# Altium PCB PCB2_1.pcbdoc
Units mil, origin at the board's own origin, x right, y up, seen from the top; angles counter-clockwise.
Board outline 2187.3 x 2736.54 mil, 4 copper layers (Top Layer, 3.3V, GND, Bottom Layer); 82 components, 93 nets, 404 pads, 111 vias.
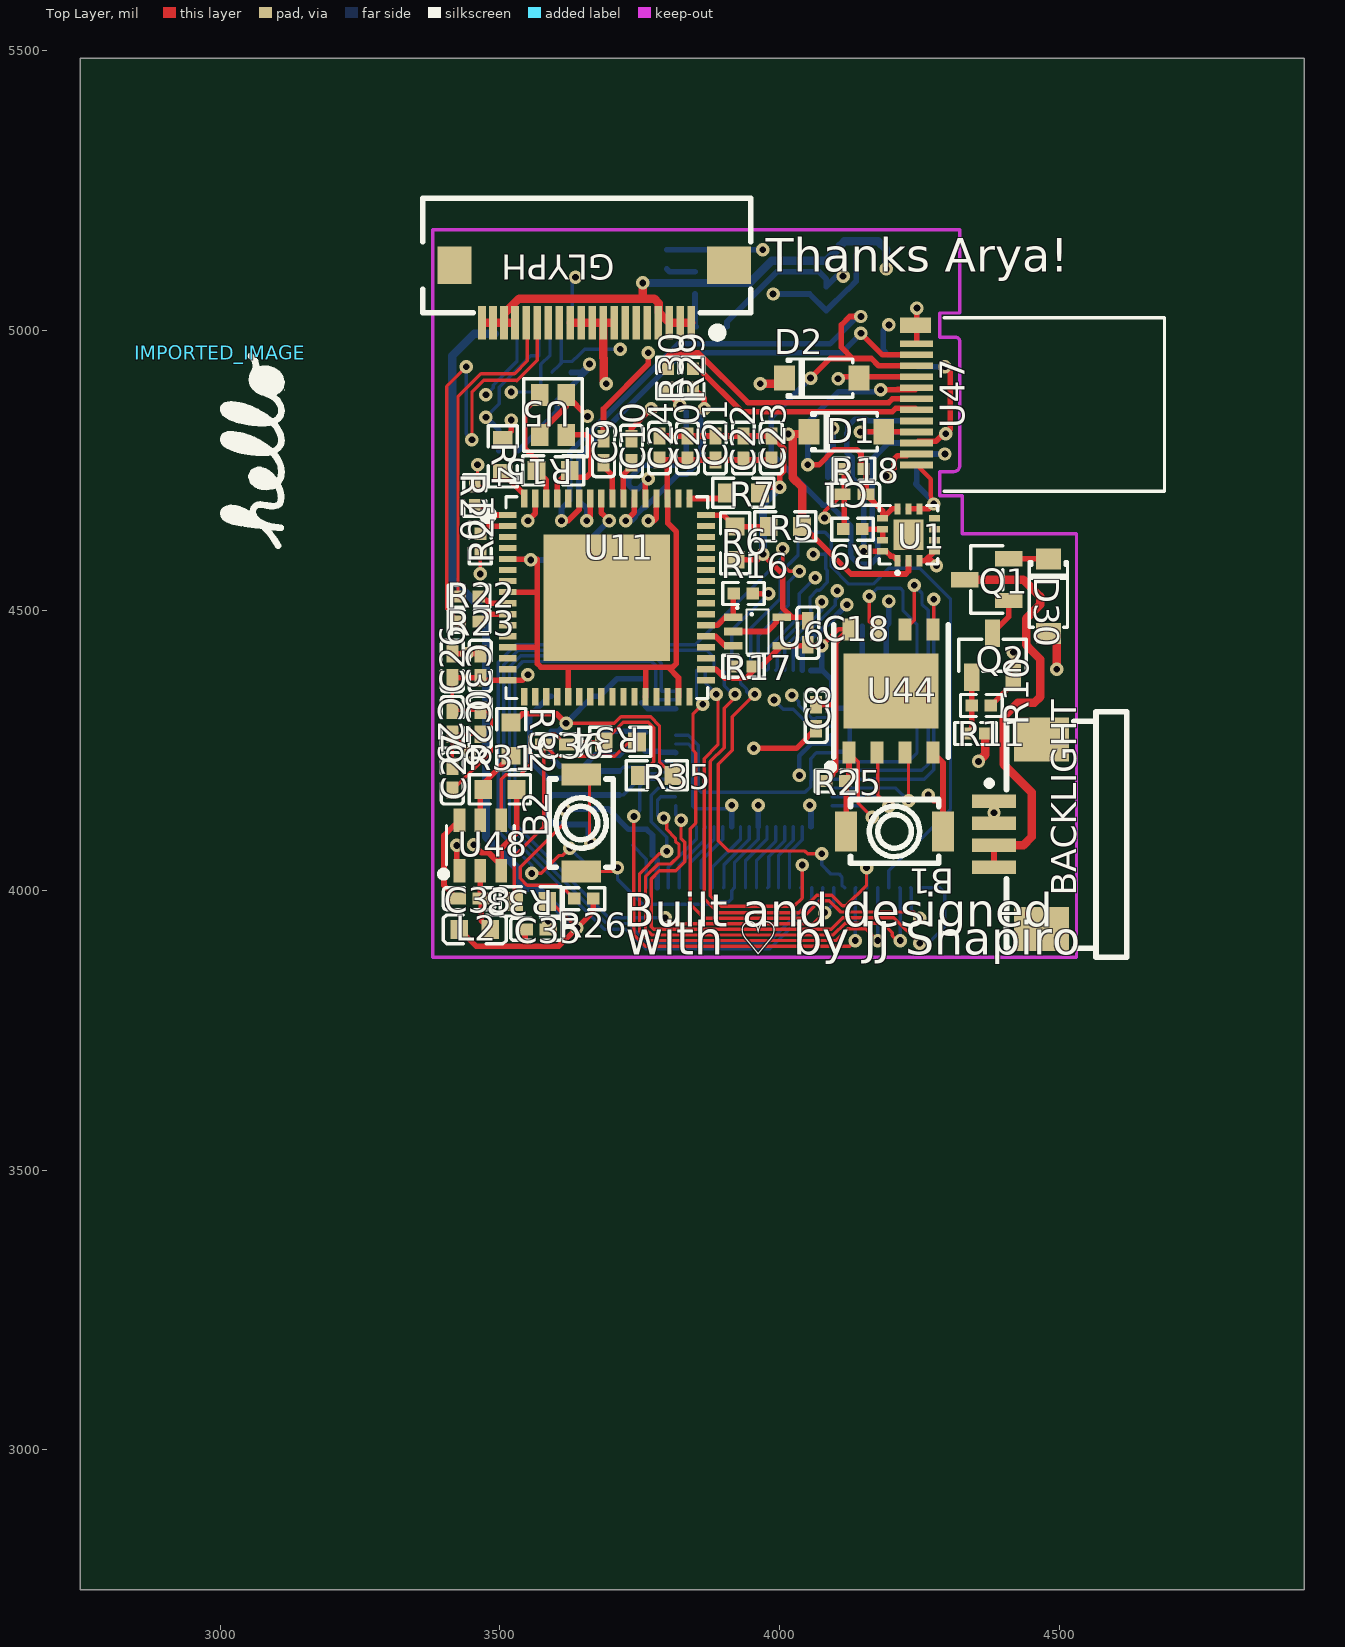
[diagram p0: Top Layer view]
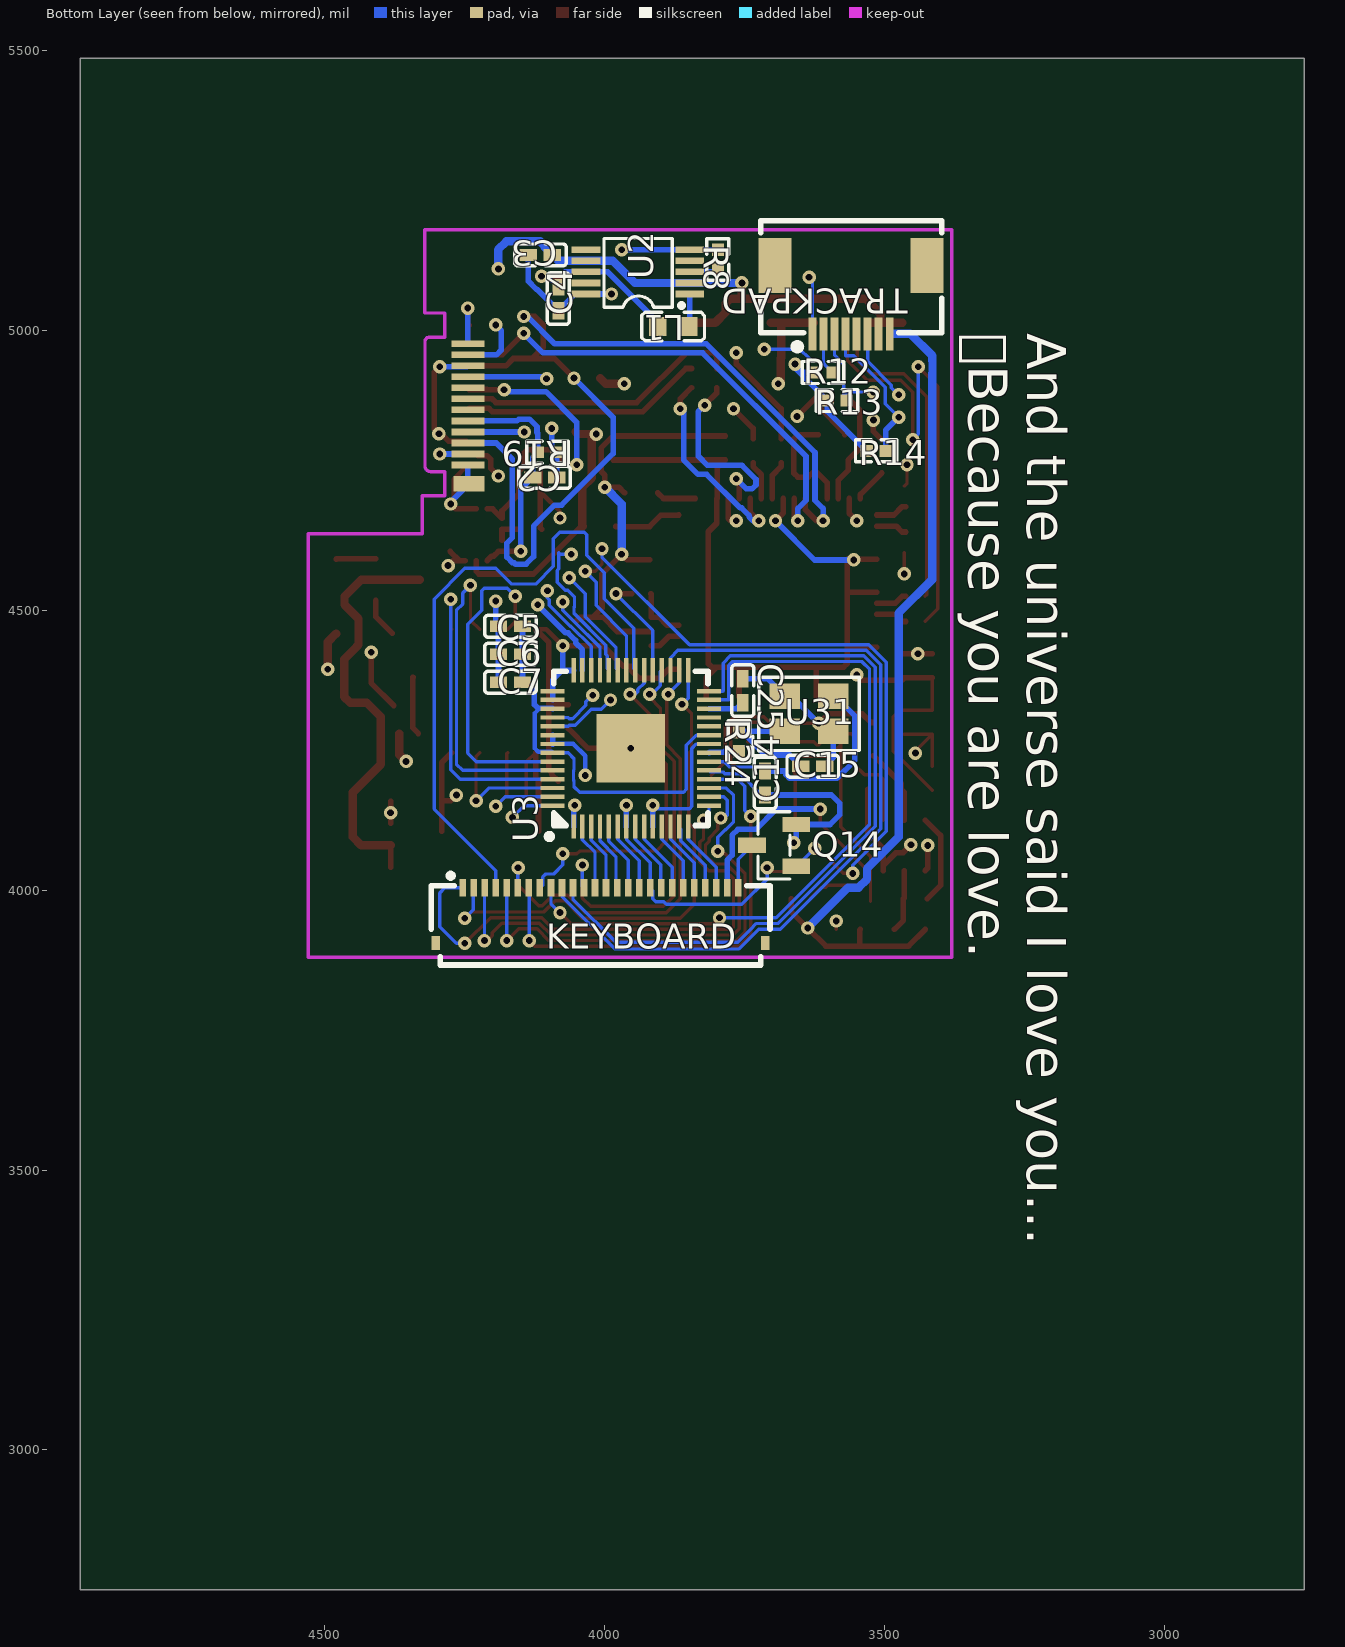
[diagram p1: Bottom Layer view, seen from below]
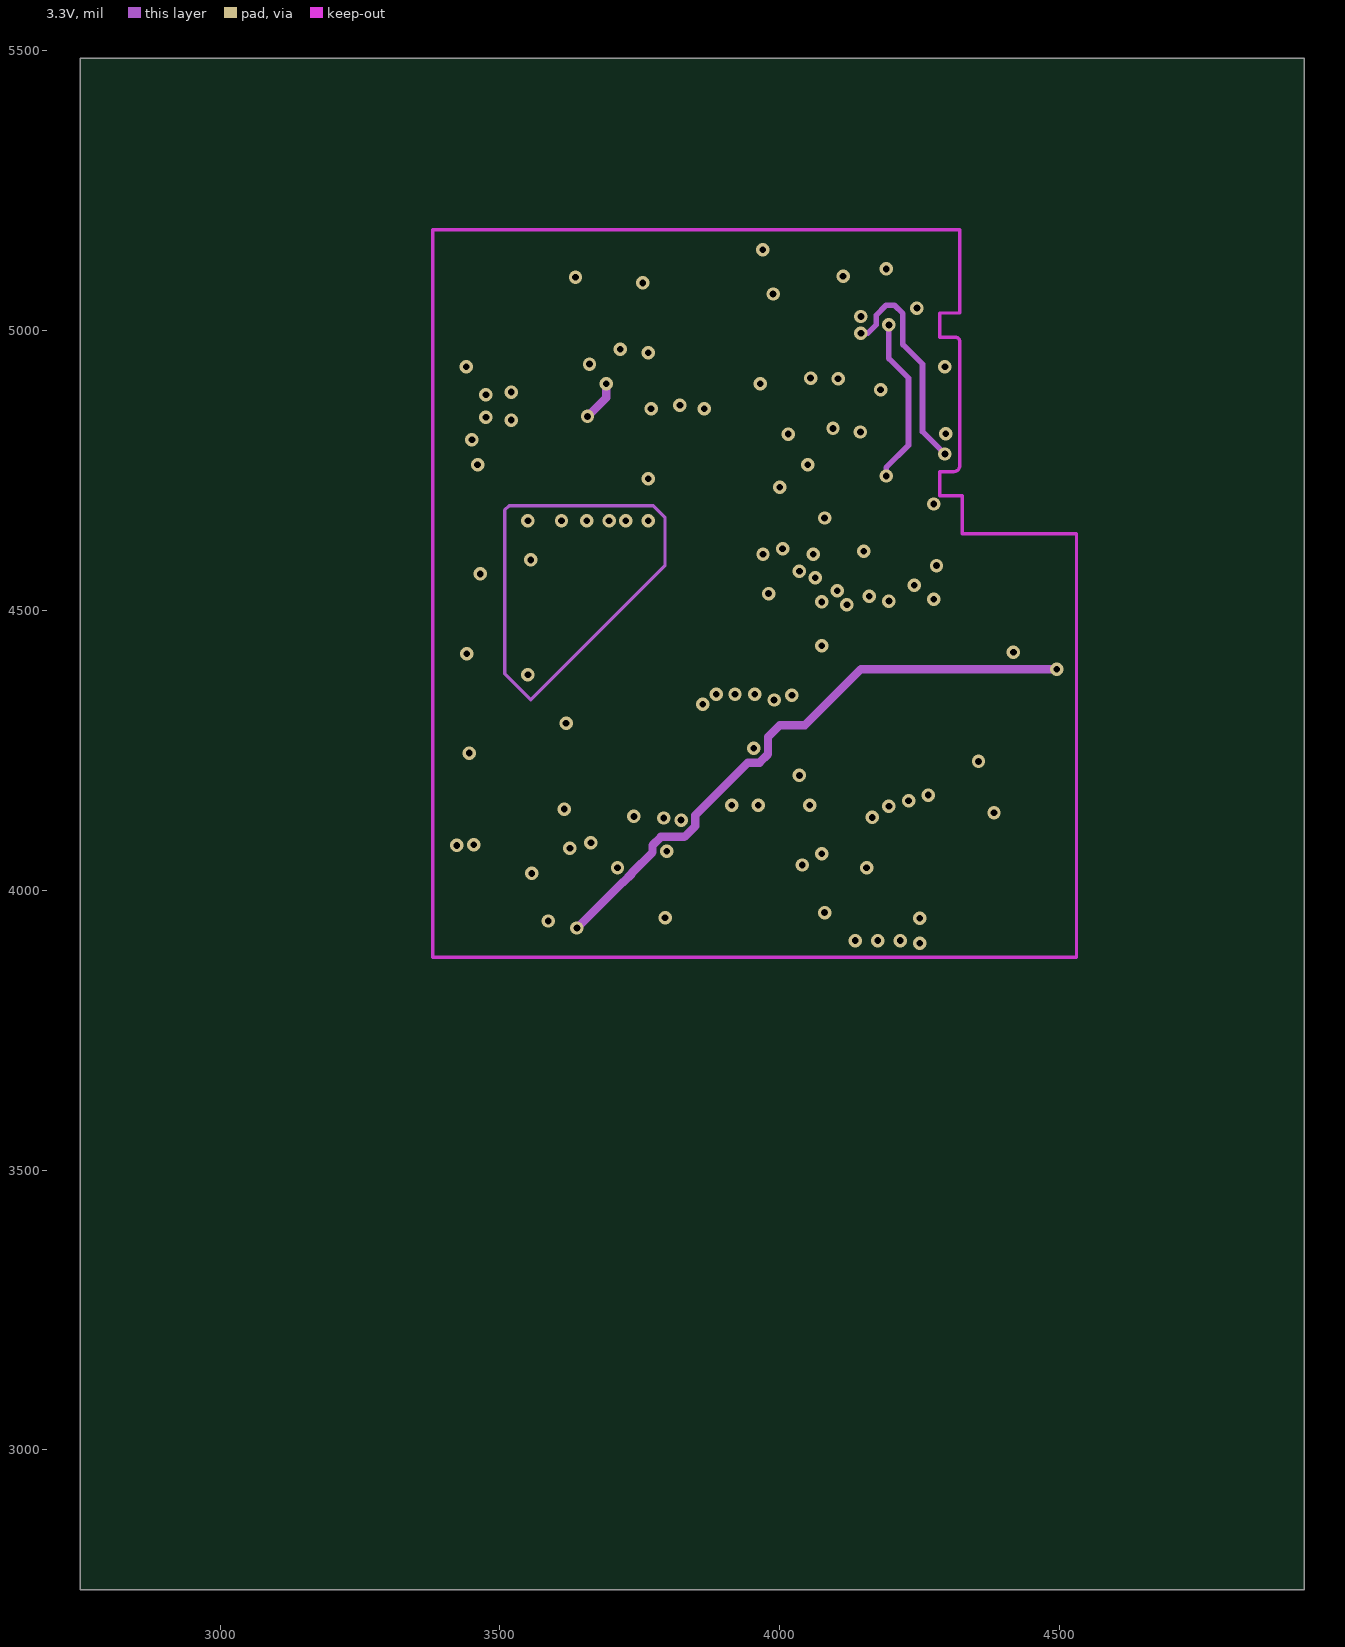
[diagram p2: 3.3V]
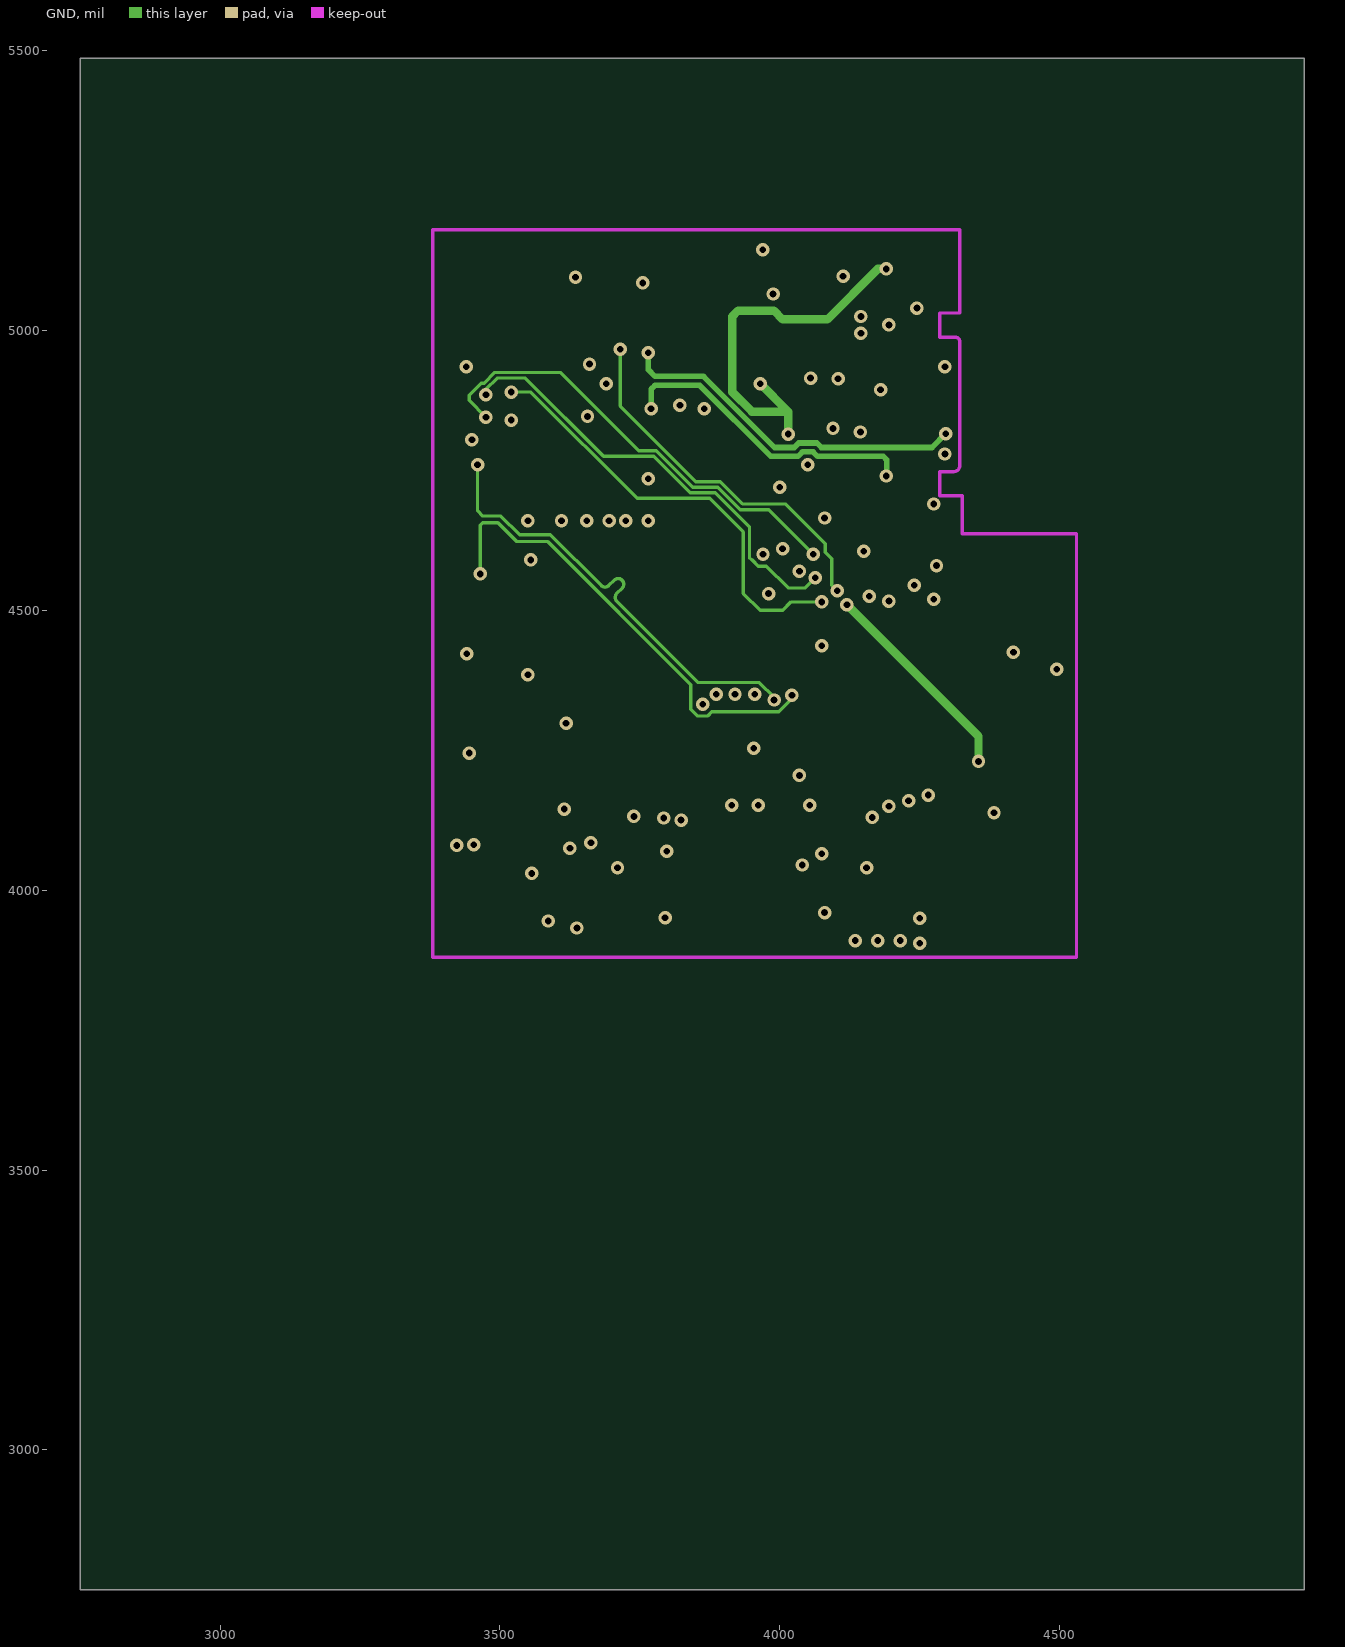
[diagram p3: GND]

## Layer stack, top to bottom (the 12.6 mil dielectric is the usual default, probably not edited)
Top Layer: signal copper (thickness not stored)
Dielectric: dielectric 12.6, FR-4, Dk 4.8
3.3V: signal copper (thickness not stored)
Dielectric: dielectric 12.6, FR-4, Dk 4.8
GND: signal copper (thickness not stored)
Dielectric: dielectric 12.6, FR-4, Dk 4.8
Bottom Layer: signal copper (thickness not stored)

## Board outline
4937.3,2750 2750,2750 2750,5486.54 4937.3,5486.54

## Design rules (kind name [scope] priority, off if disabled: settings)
BoardOutlineClearance copperThickness1oz [All] p0: genericclearance=10 ignorepadtopadclearanceinfootprint=FALSE except(0: Arc-SplitContinuation Track-SplitContinuation SMDPad-SplitContinuation THPad-SplitContinuation Via-SplitContinuation Fill-SplitContinuation Poly-SplitContinuation Region-SplitContinuation Text-SplitContinuation; 6: Track-CutoutEdge SMDPad-CutoutEdge THPad-CutoutEdge Via-CutoutEdge Region-CutoutEdge; 11.8: Track-OutlineEdge SMDPad-OutlineEdge THPad-OutlineEdge Via-OutlineEdge Fill-OutlineEdge Region-OutlineEdge Poly-OutlineEdge Text-OutlineEdge Fill-CutoutEdge)
BoardOutlineClearance copperThickness2oz [All] p0: genericclearance=10 ignorepadtopadclearanceinfootprint=FALSE except(0: Arc-SplitContinuation Track-SplitContinuation SMDPad-SplitContinuation THPad-SplitContinuation Via-SplitContinuation Fill-SplitContinuation Poly-SplitContinuation Region-SplitContinuation Text-SplitContinuation; 6: Track-CutoutEdge SMDPad-CutoutEdge THPad-CutoutEdge Via-CutoutEdge Region-CutoutEdge; 11.8: Track-OutlineEdge SMDPad-OutlineEdge THPad-OutlineEdge Via-OutlineEdge Fill-OutlineEdge Region-OutlineEdge Poly-OutlineEdge Text-OutlineEdge Fill-CutoutEdge)
Clearance copperThickness1oz [(InNet('GND') OR InNet('QSPI_SS') OR InNet('KBRD19') OR InNet('BACKLIGHT+') OR InNet('CC1') OR InNet('CC2') OR InNet('VBUS') OR InNet('+3.3V') OR InNet('$1N20') OR InNet('$1N39') OR InNet('SSTXN1') OR InNet('$1N41') OR InNet('SSTXP1') OR InNet('$1N24') OR InNet('$1N25') OR InNet('1.1V') OR InNet('$1N47') OR InNet('$1N84') OR InNet('$1N83') OR InNet('+5V') OR InNet('$1N2257') OR InNet('EINK_OLED_USB_M') OR InNet('EINK_OLED_USB_P') OR InNet('KBRD0') OR InNet('KBRD1') OR InNet('KBRD2') OR InNet('KBRD3') OR InNet('KBRD4') OR InNet('KBRD5') OR InNet('KBRD6') OR InNet('KBRD7') OR InNet('KBRD8') OR InNet('KBRD9') OR InNet('KBRD10') OR InNet('KBRD11') OR InNet('KBRD12') OR InNet('KBRD13') OR InNet('KBRD14') OR InNet('KBRD15') OR InNet('KBRD16') OR InNet('KBRD18') OR InNet('KBRD17') OR InNet('KBRD20') OR InNet('KBRD21') OR InNet('KBRD22') OR InNet('KBRD23') OR InNet('$1N22') OR InNet('CAPS-') OR InNet('$1N10') OR InNet('$1N27') OR InNet('$1N26') OR InNet('$1N19') OR InNet('$1N2') OR InNet('$1N1') OR InNet('$1N2142') OR InNet('$1N14') OR InNet('$1N15') OR InNet('KBRD_CTRL') OR InNet('TOUCHPAD_INT') OR InNet('TOUCHPAD_SCL') OR InNet('TOUCHPAD_SDA') OR InNet('$1N37') OR InNet('$1N36') OR InNet('$1N73') OR InNet('$1N72') OR InNet('$1N2151') OR InNet('KBRDUSB_P') OR InNet('$1N2152') OR InNet('KBRDUSB_M') OR InNet('$1N2157') OR InNet('$1N2158') OR InNet('$1N2308') OR InNet('TOUCHPAD_ID') OR InNet('INT_USBC_CTRL') OR InNet('SCL_USBC_CTRL') OR InNet('SDA_USBC_CTRL') OR InNet('QSPI_SD3') OR InNet('QSPI_SCLK') OR InNet('QSPI_SD0') OR InNet('QSPI_SD2') OR InNet('QSPI_SD1') OR InNet('SSRXN1') OR InNet('SSRXP1') OR InNet('USB_UP-') OR InNet('USB_UP+') OR InNet('$1N27720') OR InNet('$1N27715') OR InNet('$1N27575') OR InNet('$1N49028') OR InNet('$1N49024') OR InNet('$1N49243') OR InNet('$1N49255') OR InNet('$1N48925'))] p1: gap=7 ignorepadtopadclearanceinfootprint=FALSE except(4: Track-Track; 6: Track-SMDPad SMDPad-SMDPad Track-THPad SMDPad-THPad THPad-THPad Track-Via SMDPad-Via THPad-Via Via-Via SMDPad-Fill THPad-Fill Via-Fill Fill-Fill Track-Region SMDPad-Region THPad-Region Via-Region Region-Region Track-Poly SMDPad-Poly THPad-Poly Via-Poly Fill-Poly Region-Poly Poly-Poly Track-Text SMDPad-Text THPad-Text Via-Text Fill-Text Region-Text Poly-Text Text-Text; 6.9: Track-Hole SMDPad-Hole THPad-Hole Via-Hole Fill-Hole Region-Hole Poly-Hole Text-Hole Sheet-Hole; 11.8: Track-Fill Fill-Region Track-Sheet SMDPad-Sheet THPad-Sheet Via-Sheet Fill-Sheet Region-Sheet Poly-Sheet Text-Sheet)
Clearance copperThickness2oz [All] p1: gap=7 ignorepadtopadclearanceinfootprint=FALSE except(6: Track-SMDPad SMDPad-SMDPad Track-THPad SMDPad-THPad THPad-THPad Track-Via SMDPad-Via THPad-Via Via-Via SMDPad-Fill THPad-Fill Via-Fill Fill-Fill Track-Region SMDPad-Region THPad-Region Via-Region Region-Region Track-Poly SMDPad-Poly THPad-Poly Via-Poly Fill-Poly Region-Poly Poly-Poly Track-Text SMDPad-Text THPad-Text Via-Text Fill-Text Region-Text Poly-Text Text-Text; 6.9: Track-Hole SMDPad-Hole THPad-Hole Via-Hole Fill-Hole Region-Hole Poly-Hole Text-Hole Sheet-Hole; 8: Track-Track; 11.8: Track-Fill Fill-Region Track-Sheet SMDPad-Sheet THPad-Sheet Via-Sheet Fill-Sheet Region-Sheet Poly-Sheet Text-Sheet)
DiffPairsRouting differentialPair [All] p1: maxuncoupledlength=10 minlimit=6 maxlimit=6 mostfreqgap=6 toplayer_minwidth=5 toplayer_prefwidth=10 toplayer_maxwidth=100 bottomlayer_minwidth=5 bottomlayer_prefwidth=10 bottomlayer_maxwidth=100 midlayer1_minwidth=5 midlayer1_prefwidth=10 midlayer1_maxwidth=100 midlayer2_minwidth=5 midlayer2_prefwidth=10 midlayer2_maxwidth=100
PasteMaskExpansion pasteMaskExpansion [All] p1: expansion=0
PlaneConnect innerPlane [All] p1: planeconnectstyle=Relief reliefexpansion=20 reliefentries=4 reliefconductorwidth=10 reliefairgap=10
PolygonConnect copperRegion [All] p1: connectstyle=Relief reliefentries=4 reliefconductorwidth=10 polygonreliefangle="90 Angle" airgapwidth=10
RoutingVias viaSize [All] p1: viastyle="Through Hole" holewidth=12.0078 minholewidth=11.811 maxholewidth=248.0314 width=24.0158 minwidth=19.685 maxwidth=393.7008
SolderMaskExpansion solderMaskExpansion [All] p1: useseparateexpansions=TRUE expansion=2 expansionbottom=2
Width copperThickness1oz [All] p1: maxlimit=100 minlimit=5 preferedwidth=10
Width copperThickness2oz [All] p1: maxlimit=100 minlimit=8 preferedwidth=10

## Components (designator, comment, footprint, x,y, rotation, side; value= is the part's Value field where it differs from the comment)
B1 "BUTTON" SW-SMD_L3.9-W2.9-LS4.9-L 4205,4105 r180 top
B2 "BUTTON" SW-SMD_L3.9-W2.9-LS4.9-L 3645,4120 r90 top
BACKLIGHT "FPC-1.0-4P" FPC-SMD_4P-P1.00_HDGC_1.0K-ES-4PWB 4425,4100 r90 top
C1 "400pF" C0402 4132.5,4707.5 r180 top
C2 "400pF" C0402 4107.5,4737.5 r0 bottom
C3 "1uF" C0402 4115,5135 r180 bottom
C4 "10uF" C0402 4083.02,5056.98 r270 bottom
C5 "470nF" C0402 4168.47,4471.53 r180 bottom
C6 "470nF" C0402 4168.47,4421.53 r180 bottom
C7 "470nF" C0402 4168.47,4371.53 r180 bottom
C8 "0.1uF" C0402 4065,4310 r90 top
C9 "0.1uF" C0402 3685,4785 r90 top
C10 "0.1uF" C0402 3735,4785 r90 top
C14 "15pF" C0402 3713.47,4191.53 r270 bottom
C15 "15pF" C0402 3628.47,4221.53 r180 bottom
C18 "0.1uF" C0402 4050,4460 r270 top
C20 "0.1uF" C0402 3835,4790 r90 top
C21 "0.1uF" C0402 3885,4790 r90 top
C22 "0.1uF" C0402 3935,4790 r90 top
C23 "0.1uF" C0402 3985,4790 r90 top
C24 "10uF" C0402 3785,4790 r90 top
C25 "0.1uF" C0402 3753.47,4356.53 r270 bottom
C26 "10uF" C0402 3465,4400.81 r90 top
C27 "0.1uF" C0402 3415,4200 r90 top
C28 "0.1uF" C0402 3465,4300 r270 top
C29 "0.1uF" C0402 3415,4300 r270 top
C30 "0.1uF" C0402 3415,4400.81 r90 top
C33 "0.1uF" C0402 3445,3985 r180 top
C35 "10uF" C0402 3565,3930 r0 top
C36 "75pF" C0402 3600,4260 r0 top
D1 "1N4007W" SOD-123_L2.8-W1.8-LS3.7-RD 4119.04,4818.79 r0 top
D2 "1N4007W" SOD-123_L2.8-W1.8-LS3.7-RD 4075,4915 r0 top
D30 "1N4007W" SOD-123_L2.8-W1.8-LS3.7-RD 4480,4525 r270 top
GLYPH "HC-FPC-0.5-20P-FH20" FPC-SMD_20P-P0.50_HC-FPC-0.5-20P-FH20 3655,5065 r180 top
IMPORTED_IMAGE "IMPORTED_IMAGE" IMPORTED_IMAGE 3000,4960 r0 top
KEYBOARD "046809626210846+" FPC-SMD_26P-P0.50_046809626210846 4007.6,3955 r180 bottom
L1 "47uH" L0603 3878.02,5006.98 r0 bottom
L2 "47uH" L0603 3455,3930 r0 top
Q1 "CJ2305" SOT-23-3_L2.9-W1.3-P1.90-LS2.4-BR 4370,4555 r0 top
Q2 "BC817" SOT-23-3_L2.9-W1.3-P1.90-LS2.4-BR 4380,4420 r270 top
Q14 "BC817" SOT-23-3_L2.9-W1.3-P1.90-LS2.4-BR 3697.6,4080 r180 bottom
R4 "9.53k±1%" R0603 3505,4775 r270 top
R5 "90.9k±1%" R0603 4010,4650 r180 top
R6 "10k±1%" R0603 3920,4620 r270 top
R7 "90.9k±1%" R0603 3935,4710 r180 top
R8 "56.2k" R0402 3798.02,5126.98 r270 bottom
R9 "5.1k" R0402 4130,4645 r180 top
R10 "5.1k" R0402 4360,4330 r180 top
R11 "1k" R0402 4350,4280 r180 top
R12 "4.7k - 0603" R0402 3610,4925 r180 bottom
R13 "4.7k - 0603" R0402 3585,4875 r180 bottom
R14 "4.7k" R0402 3515,4785 r180 bottom
R15 "1M" R0603 3595,4750 r0 top
R16 "4.7k" R0402 3935,4530 r0 top
R17 "4.7k" R0402 3935,4400 r0 top
R18 "5.1k" R0402 4132.5,4752.5 r0 top
R19 "5.1k" R0402 4102.5,4782.5 r0 bottom
R20 "22" R0402 3455,4705 r270 top
R21 "22" R0402 3465,4620 r90 top
R22 "22" R0402 3445,4525 r0 top
R23 "22" R0402 3445,4480 r0 top
R24 "1k" R0402 3760.07,4265.3 r270 bottom
R25 "5.1k" R0402 4100,4195 r0 top
R26 "1k" R0402 3650,3985 r0 top
R29 "22" R0402 3845,4915 r90 top
R30 "22" R0402 3800,4915 r90 top
R31 "511k" R0603 3500,4180 r0 top
R32 "511k" R0603 3520,4270 r270 top
R33 "49.9k" R0603 3555,3980 r180 top
R34 "100k" R0603 3715,4265 r180 top
R35 "13.3k" R0603 3780,4205 r0 top
TRACKPAD "TEMPORARY 8-PIN CONN" CONN-SMD_8P-P0.50_HC-FPC-0.5-8P-FHH20 3560,5055 r0 bottom
U1 "FUSB302BVMPX" MLP-14_L2.5-W2.5-P0.50-BL-EP 4230,4635 r0 top
U2 "LM5165YQDGSRQ1" VSSOP-10_L3.0-W3.0-P0.50-LS4.9-BL 3940.94,5104.61 r90 bottom
U3 "RP2040" LQFN-56_L7.0-W7.0-P0.4-EP 3953.43,4253.38 r90 bottom
U5 "24MHz" OSC-SMD_4P-XRCGB24M000F0L00R0 3594.89,4849 r90 top
U6 "24LC02BT-I/LT" SC-70-5_L2.0-W1.3-P0.65-LS2.1-BR 3960.03,4462.27 r180 top
U11 "TUSB8044ARGCT" VQFN-64_L9.0-W9.0-P0.50-TL-EP5.8 3690.97,4522.65 r0 top
U31 "ABM8-272-T3" CRYSTAL-SMD_4P-L3.2-W2.5-BL-2 3635.07,4315.3 r180 bottom
U44 "W25Q128JVPIM" WSON-8_L5.0-W6.0-P1.27-BL-EP 4198.66,4355.89 r0 top
U47 "TYPE-C 24P-GTJB 040" USB-C-SMD_TYPE-C-24P-GTJB-040 4243.6,4867.9 r90 top
U48 "TPS54302DDCR_C311983" SOT-23-6_L2.9-W1.6-P0.95-LS2.8-BL 3465,4080 r0 top

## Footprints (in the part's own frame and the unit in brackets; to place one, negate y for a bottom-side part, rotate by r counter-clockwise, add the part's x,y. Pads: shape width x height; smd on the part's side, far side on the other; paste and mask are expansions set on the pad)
C0402 [mm]
  rect 0.79x0.54 smd: 1(0.545,0) 2(-0.545,0)
  silkscreen extent -1.17,-0.5 1.17,0.5
CONN-SMD_8P-P0.50_HC-FPC-0.5-8P-FHH20 [mm]
  rect 0.35x1.5 smd: 1(1.75,1.55) 2(1.25,1.55) 3(0.75,1.55) 4(0.25,1.55) 5(-0.25,1.55) 6(-0.75,1.55) 7(-1.25,1.55) 8(-1.75,1.55)
  rect 1.5x2.5 smd: 9(-3.45,-1.55) 10(3.45,-1.55)
  silkscreen extent -4.12,-3.58 4.09,2.44
CRYSTAL-SMD_4P-L3.2-W2.5-BL-2 [mm]
  rect 1.4x1.15 smd: 1(-1.1,-0.8) 2(1.1,-0.8) 3(1.1,0.8) 4(-1.1,0.8)
  silkscreen extent -2.54,-1.9 2.29,1.65
FPC-SMD_4P-P1.00_HDGC_1.0K-ES-4PWB [mm]
  rect 0.6x2 smd: 1(1.5,1.075) 2(0.5,1.075) 3(-0.5,1.075) 4(-1.5,1.075)
  rect 2x2.5 smd: 5(-4.3,-1.075) 6(4.3,-1.075)
  silkscreen extent -5.59,-4.95 5.55,1.42
FPC-SMD_20P-P0.50_HC-FPC-0.5-20P-FH20 [mm]
  rect 0.35x1.5 smd: 1(-4.75,1.3) 2(-4.25,1.3) 3(-3.75,1.3) 4(-3.25,1.3) 5(-2.75,1.3) 6(-2.25,1.3) 7(-1.75,1.3) 8(-1.25,1.3) 9(-0.75,1.3) 10(-0.25,1.3) 11(0.25,1.3) 12(0.75,1.3) 13(1.25,1.3) 14(1.75,1.3) 15(2.25,1.3) 16(2.75,1.3) 17(3.25,1.3) 18(3.75,1.3) 19(4.25,1.3) 20(4.75,1.3)
  rect 1.542x1.7 smd: 21(5.992,-1.3)
  rect 2x1.7 smd: 22(-6.45,-1.3)
  silkscreen extent -7.45,-4.36 7.45,2.16
FPC-SMD_26P-P0.50_046809626210846 [mm]
  rect 0.3x0.8 smd: 1(-6.25,1.25) 2(-5.75,1.25) 3(-5.25,1.25) 4(-4.75,1.25) 5(-4.25,1.25) 6(-3.75,1.25) 7(-3.25,1.25) 8(-2.75,1.25) 9(-2.25,1.25) 10(-1.75,1.25) 11(-1.25,1.25) 12(-0.75,1.25) 13(-0.25,1.25) 14(0.25,1.25) 15(0.75,1.25) 16(1.25,1.25) 17(1.75,1.25) 18(2.25,1.25) 19(2.75,1.25) 20(3.25,1.25) 21(3.75,1.25) 22(4.25,1.25) 23(4.75,1.25) 24(5.25,1.25) 25(5.75,1.25) 26(6.25,1.25)
  rect 0.4x0.635 smd: 27(7.475,-1.25) 28(-7.475,-1.25)
  silkscreen extent -7.69,-2.25 7.69,2.03
IMPORTED_IMAGE [mil]
  silkscreen extent 0,-350 116,0
L0603 [mm]
  rect 0.8x0.864 smd: 1(-0.7,0) 2(0.7,0)
  silkscreen extent -1.42,-0.65 1.42,0.65
LQFN-56_L7.0-W7.0-P0.4-EP [mm]
  rect 1.1x0.2 smd: 1(-3.55,2.6) 2(-3.55,2.2) 3(-3.55,1.8) 4(-3.55,1.4) 5(-3.55,1) 6(-3.55,0.6) 7(-3.55,0.2) 8(-3.55,-0.2) 9(-3.55,-0.6) 10(-3.55,-1) 11(-3.55,-1.4) 12(-3.55,-1.8) 13(-3.55,-2.2) 14(-3.55,-2.6) 29(3.55,-2.6) 30(3.55,-2.2) 31(3.55,-1.8) 32(3.55,-1.4) 33(3.55,-1) 34(3.55,-0.6) 35(3.55,-0.2) 36(3.55,0.2) 37(3.55,0.6) 38(3.55,1) 39(3.55,1.4) 40(3.55,1.8) 41(3.55,2.2) 42(3.55,2.6)
  rect 0.2x1.1 smd: 15(-2.6,-3.55) 16(-2.2,-3.55) 17(-1.8,-3.55) 18(-1.4,-3.55) 19(-1,-3.55) 20(-0.6,-3.55) 21(-0.2,-3.55) 22(0.2,-3.55) 23(0.6,-3.55) 24(1,-3.55) 25(1.4,-3.55) 26(1.8,-3.55) 27(2.2,-3.55) 28(2.6,-3.55) 43(2.6,3.55) 44(2.2,3.55) 45(1.8,3.55) 46(1.4,3.55) 47(1,3.55) 48(0.6,3.55) 49(0.2,3.55) 50(-0.2,3.55) 51(-0.6,3.55) 52(-1,3.55) 53(-1.4,3.55) 54(-1.8,3.55) 55(-2.2,3.55) 56(-2.6,3.55)
  rect 3.1x3.1 smd: 57(0,0)
  silkscreen extent -4.13,-3.5 3.5,3.83
MLP-14_L2.5-W2.5-P0.50-BL-EP [mm]
  rect 0.28x0.505 smd: 1(-0.5,-1.178) 2(0,-1.178) 3(0.5,-1.178) 8(0.5,1.178) 9(0,1.178) 10(-0.5,1.178)
  rect 0.505x0.28 smd: 4(1.178,-0.75) 5(1.178,-0.25) 6(1.178,0.25) 7(1.178,0.75) 11(-1.178,0.75) 12(-1.178,0.25) 13(-1.178,-0.25) 14(-1.178,-0.75)
  rect 1.375x1.375 smd: 15(0,0)
  silkscreen extent -1.33,-1.8 1.33,1.33
OSC-SMD_4P-XRCGB24M000F0L00R0 [mm]
  rect 1x0.8 smd: 1(-0.9,-0.6) 2(0.9,-0.6) 3(0.9,0.6) 4(-0.9,0.6)
  silkscreen extent -1.89,-1.56 1.65,1.33
R0402 [mm]
  rect 0.566x0.54 smd: 1(-0.433,0) 2(0.433,0)
  silkscreen extent -0.94,-0.5 0.94,0.5
R0603 [mil]
  rect 31.75x34.02 smd: 1(-29.66,0) 2(29.66,0)
  silkscreen extent -55,-26 55,26
SC-70-5_L2.0-W1.3-P0.65-LS2.1-BR [mm]
  rect 0.85x0.35 smd: 1(1.1,-0.65) 2(1.1,0) 3(1.1,0.65) 4(-1.1,0.65) 5(-1.1,-0.65)
  silkscreen extent -0.5,-1.12 0.96,1
SOD-123_L2.8-W1.8-LS3.7-RD [mm]
  rect 0.95x1.15 smd: 1(-1.692,0) 2(1.692,0)
  silkscreen extent -1.58,-0.87 1.41,0.87
SOT-23-3_L2.9-W1.3-P1.90-LS2.4-BR [mm]
  rect 1.25x0.7 smd: 1(1,-0.95) 2(1,0.95) 3(-1,0)
  silkscreen extent -0.73,-1.53 0.73,1.53
SOT-23-6_L2.9-W1.6-P0.95-LS2.8-BL [mil]
  rect 20.95x42.2 smd: 1(-37.4,-45.24) 2(0,-45.24) 3(37.4,-45.24) 4(37.4,45.24) 5(0,45.24) 6(-37.4,45.24)
  silkscreen extent -72,-57 61,35
SW-SMD_L3.9-W2.9-LS4.9-L [mm]
  rect 1x1.8 smd: 1(-2.2,0) 2(2.2,0)
  silkscreen extent -2,-1.45 2,1.45
USB-C-SMD_TYPE-C-24P-GTJB-040 [mm]
  rect 0.7x1.4 smd: 25(3.6,0.025)
  rect 0.7x1.4 smd far side: 26(-3.6,0.025)
  rect 0.3x1.5 smd: A1(2.75,-0.025) A2(2.25,-0.025) A3(1.75,-0.025) A4(1.25,-0.025) A5(0.75,-0.025) A6(0.25,-0.025) A7(-0.25,-0.025) A8(-0.75,-0.025) A9(-1.25,-0.025) A10(-1.75,-0.025) A11(-2.25,-0.025) A12(-2.75,-0.025)
  rect 0.3x1.5 smd far side: B1(-2.75,-0.025) B2(-2.25,-0.025) B3(-1.75,-0.025) B4(-1.25,-0.025) B5(-0.75,-0.025) B6(-0.25,-0.025) B7(0.25,-0.025) B8(0.75,-0.025) B9(1.25,-0.025) B10(1.75,-0.025) B11(2.25,-0.025) B12(2.75,-0.025)
  Board Outline Layer lines w0.15: -4.15,-1.075 -3.05,-1.075 ; -4.15,-1.075 -4.15,-1.975 -4.15,-1.075 ; -4.15,-1.075 -3.05,-1.075 ; -3.05,-1.075 -3.05,-1.7 ; -3.05,-1.075 -3.05,-1.7 ; 3.05,-1.075 3.05,-1.785 ; 3.05,-1.075 4.15,-1.075 ; 3.05,-1.075 3.05,-1.785 ; 3.05,-1.075 4.15,-1.075 ; 4.15,-1.075 4.15,-1.975 4.15,-1.075 ; -3.05,-1.7 -3.05,-1.719 ; -3.05,-1.7 -3.05,-1.719 ; -3.05,-1.719 ccw(c-2.794,-1.719) -2.794,-1.975 cw(c-2.794,-1.719) -3.05,-1.719 ; 3.05,-1.785 cw(c2.86,-1.785) 2.86,-1.975 ; 3.05,-1.785 cw(c2.86,-1.785) 2.86,-1.975 ; 2.86,-1.975 -2.741,-1.975 2.86,-1.975 ; -3.937,-1.075 cw(c-3.937,-1.077) -3.935,-1.077 ccw(c-3.937,-1.077) -3.937,-1.075
  silkscreen extent -3.94,-11.27 3.94,-1.27
VQFN-64_L9.0-W9.0-P0.50-TL-EP5.8 [mm]
  rect 0.8x0.28 smd: 1(-4.5,3.75) 2(-4.5,3.25) 3(-4.5,2.75) 4(-4.5,2.25) 5(-4.5,1.75) 6(-4.5,1.25) 7(-4.5,0.75) 8(-4.5,0.25) 9(-4.5,-0.25) 10(-4.5,-0.75) 11(-4.5,-1.25) 12(-4.5,-1.75) 13(-4.5,-2.25) 14(-4.5,-2.75) 15(-4.5,-3.25) 16(-4.5,-3.75) 33(4.5,-3.75) 34(4.5,-3.25) 35(4.5,-2.75) 36(4.5,-2.25) 37(4.5,-1.75) 38(4.5,-1.25) 39(4.5,-0.75) 40(4.5,-0.25) 41(4.5,0.25) 42(4.5,0.75) 43(4.5,1.25) 44(4.5,1.75) 45(4.5,2.25) 46(4.5,2.75) 47(4.5,3.25) 48(4.5,3.75)
  rect 0.28x0.8 smd: 17(-3.75,-4.5) 18(-3.25,-4.5) 19(-2.75,-4.5) 20(-2.25,-4.5) 21(-1.75,-4.5) 22(-1.25,-4.5) 23(-0.75,-4.5) 24(-0.25,-4.5) 25(0.25,-4.5) 26(0.75,-4.5) 27(1.25,-4.5) 28(1.75,-4.5) 29(2.25,-4.5) 30(2.75,-4.5) 31(3.25,-4.5) 32(3.75,-4.5) 49(3.75,4.5) 50(3.25,4.5) 51(2.75,4.5) 52(2.25,4.5) 53(1.75,4.5) 54(1.25,4.5) 55(0.75,4.5) 56(0.25,4.5) 57(-0.25,4.5) 58(-0.75,4.5) 59(-1.25,4.5) 60(-1.75,4.5) 61(-2.25,4.5) 62(-2.75,4.5) 63(-3.25,4.5) 64(-3.75,4.5)
  rect 5.75x5.75 smd: 65(0,0)
  silkscreen extent -5.59,-4.58 4.58,4.58
VSSOP-10_L3.0-W3.0-P0.50-LS4.9-BL [mm]
  rect 0.3x1.3 smd: 1(-1,-2.35) 2(-0.5,-2.35) 3(0,-2.35) 4(0.5,-2.35) 5(1,-2.35) 6(1,2.35) 7(0.5,2.35) 8(0,2.35) 9(-0.5,2.35) 10(-1,2.35)
  silkscreen extent -1.62,-2.08 1.52,1.54
WSON-8_L5.0-W6.0-P1.27-BL-EP [mm]
  rect 0.6x1 smd: 1(-1.905,-2.8) 2(-0.635,-2.8) 3(0.635,-2.8) 4(1.905,-2.8) 5(1.905,2.8) 6(0.635,2.8) 7(-0.635,2.8) 8(-1.905,2.8)
  rect 4.3x3.4 smd: 9(0,0)
  silkscreen extent -2.9,-3.6 2.6,3

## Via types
v1: diameter 24.02, hole 12.01, Top Layer to Bottom Layer, 111 vias

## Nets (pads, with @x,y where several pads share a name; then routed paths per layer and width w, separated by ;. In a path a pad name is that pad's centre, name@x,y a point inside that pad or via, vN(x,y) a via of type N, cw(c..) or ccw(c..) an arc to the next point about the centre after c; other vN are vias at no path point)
1.1V: C20.2 C21.2 C22.2 C23.2 C24.2 U11.5 U11.8 U11.13 U11.21 U11.28 U11.31 U11.51 U11.57 | length 1560.1
  Top Layer w10: U11.13 3565.49,4434.07 3566.8,4432.76 ; U11.8 3566.46,4532.49 3566.8,4532.15 ; U11.5 v1@3555.34,4591.55 ; v1(3555,4590) 3555,4591.21 v1@3555.34,4591.55 ; U11.21 3622.07,4396.56 3620.16,4398.48 ; U11.57 3681.13,4673.87 v1(3695,4660) ; U11.28 3760.25,4345.86 3760.25,4398.48 ; U11.31 3818.92,4379.55 3800,4398.48 ; C23.2 C22.2 C21.2 C20.2 C24.2 3799.24,4754.3 U11.51 3800,4699.05 3800,4655.53 3815.14,4640.39 3815.14,4404.91 3808.71,4398.48 3800,4398.48 ; v1@3555.34,4591.55 3566.8,4591.55 3566.8,4532.15 ; 3566.8,4432.76 3566.8,4532.15 ; 3566.8,4432.76 3566.8,4404.91 3573.23,4398.48 3620.16,4398.48 ; 3620.16,4398.48 3760.25,4398.48 ; 3760.25,4398.48 3800,4398.48
  Bottom Layer w10: v1(3555,4590) 3625,4590 v1(3695,4660)
$1N1: R5.2 R6.1 U11.48 | length 120.9
  Top Layer w10: U11.48 3868.43,4670 3899.66,4670 R6.1 3980,4649.66 R5.2
$1N2: R4.2 U11.64 | length 61.4
  Top Layer w10: R4.2 3543.33,4707.01 U11.64
$1N10: L1.1 U2.1 | length 59.1
  Bottom Layer w10: U2.1 3848.42,5009.01 L1.1
$1N14: R8.2 U2.3 | length 52.6
  Bottom Layer w10: R8.2 3803.36,5104.6 U2.3
$1N15: R9.1 U1.12 U1.13 | length 51.3
  Top Layer w10: R9.1@4152.04,4645 4183.48,4645 U1.12 U1.13
$1N19: Q14.1 U3.36 | length 1406.4
  Top Layer w6: v1(3557.02,4029.97) 3573.76,4029.97 3605.85,4062.06 3612.06,4062.06 v1(3625,4075) ; v1(4005,4610) 4005,4581.99 4016.99,4570 v1(4035,4570)
  Bottom Layer w6: v1(3557.02,4029.97) 3557.02,4044.95 3496.96,4105 3496.96,4406.97 3528.64,4438.65 3848.65,4438.65 4005,4595 v1(4005,4610) ; v1(3625,4075) 3657.4,4042.6 Q14.1 ; U3.36 3961.3,4455 4015,4508.7 4015,4550 v1(4035,4570)
$1N20: C5.1 C6.1 C7.1 U3.23 U3.45 U3.50 | length 724.5
  Bottom Layer w6: U3.23 3836.21,4277 3854.32,4258.89 3854.32,4180 3859.32,4175 4045,4175 4055,4185 4055,4195.31 4055.99,4196.3 4055.99,4213.7 4055,4214.69 4055,4235 4065.5,4245.5 U3.50
  Bottom Layer w8: U3.50 4095.01,4247.33 4118.97,4247.33 4124.82,4253.18 4124.82,4316.57 4119.39,4322.01 4119.39,4325.07
  Bottom Layer w10: U3.45 4094.01,4325.07 4119.39,4325.07 4125.82,4331.51 4125.82,4356.88 4140.48,4371.53 C7.1 C6.1 C5.1
$1N22: KEYBOARD.25 R26.1 | length 543
  Top Layer w6: v1(3615,4145) 3615,4119.69 3536.02,4040.71 3536.02,4021.27 3548.29,4009.01 3601.56,4009.01 3605.85,4004.72 3613.24,4004.72 R26.1
  Bottom Layer w10: v1(3615,4145) 3693.62,4145 3729.84,4108.78 3762.11,4108.78 3772.56,4098.33 3772.56,4062.61 3781.22,4053.95 KEYBOARD.25
$1N24: C14.2 U3.20 U31.3 | length 422.4
  Bottom Layer w6: C14.2 3720.47,4220 3776.93,4220 3786.7,4229.76 U3.20
  Bottom Layer w10: U31.3 3589.03,4346.8 3553.22,4311 3553.22,4231.78 3585.08,4199.92 3670.03,4199.92 3676.46,4206.35 3676.46,4212.92 3676.54,4212.99 C14.2
$1N25: C15.2 R24.1 U31.1 | length 217.6
  Bottom Layer w10: C15.2 3669.93,4241.53 3713.47,4241.53 3754.27,4282.34 R24.1 3758.6,4283.81 U31.1
$1N26: Q2.1 R10.2 R11.2 | length 104.9
  Top Layer w10: R11.2 4342.96,4290 R10.2 4342.96,4380.27 Q2.1
$1N27: Q1.1 Q2.3 | length 70.4
  Top Layer w10: Q2.3 4409.37,4488.74 Q1.1
$1N36: R15.1 U5.3 U11.62 | length 211.5
  Top Layer w10: U5.3 3544.54,4857.7 3544.54,4789.34 3565.34,4768.54 R15.1 3582.7,4732.64 U11.62
$1N37: R15.2 U5.1 U11.61 | length 212.7
  Top Layer w10: U11.61 3602.39,4727.73 R15.2 3636.73,4737.93 3655,4737.93 3662.07,4745 3662.07,4806.5 3655,4813.57 U5.1
$1N39: C9.2 U11.56 | length 70.3
  Top Layer w10: C9.2 3685,4756.91 3700.81,4741.1 U11.56
$1N41: C10.2 U11.55 | length 69.7
  Top Layer w10: U11.55 3720.5,4742.41 3735,4756.91 C10.2
$1N47: C25.1 U3.26 | length 64.7
  Bottom Layer w10: C25.1 3764.3,4324.24 U3.26
$1N72: R17.1 U6.3 U11.37 | length 55.6
  Top Layer w10: U11.37 3885.26,4453.75 3902.32,4436.68 U6.3
$1N73: R16.1 U6.1 U11.38 | length 97.2
  Top Layer w10: U11.38 3888.44,4473.44 3902.86,4487.86 U6.1 3916.72,4528.76 R16.1
$1N83: D2.2 U47.A4 U47.B9 | length 283.8
  Top Layer w10: v1(4104.04,4913.79) 4107.33,4917.09 U47.A4
  Bottom Layer w10: v1(4104.04,4913.79) 4107.33,4917.09 U47.B9
$1N84: D1.2 U47.A9 U47.B4 | length 201.1
  Top Layer w10: v1(4144.04,4818.66) 4144.17,4818.79 D1.2 4244.42,4818.79 U47.A9
  Bottom Layer w10: v1(4144.04,4818.66) U47.B4
$1N2142: R7.2 U11.49 | length 70.9
  Top Layer w10: U11.49 3895.15,4699.81 R7.2
$1N2151: R20.2 U11.1 | length 57.9
  Top Layer w10: R20.2@3462.04,4685 3468.67,4685 3483.38,4670.29 U11.1
$1N2152: R21.2 U11.2 | length 56.2
  Top Layer w10: R21.2@3462.04,4640 3468.67,4640 3479.27,4650.6 U11.2
$1N2157: R22.2 U11.9 | length 56.8
  Top Layer w10: R22.2 3468.67,4525 3480.86,4512.81 U11.9
$1N2158: R23.2 U11.10 | length 57.2
  Top Layer w10: R23.2 3468.67,4480 3481.79,4493.12 U11.10
$1N2257: D30.1 Q1.2 | length 70.9
  Top Layer w10: Q1.2 4479.23,4592.4 D30.1
$1N2308: R24.2 U3.21 | length 54.7
  Bottom Layer w10: R24.2 3785.53,4248.26 3787.46,4246.33 3812.84,4246.33 U3.21
$1N27575: U47.B8
$1N27715: R30.1 U11.53 | length 349.5
  Top Layer w10: U11.53 3759.87,4729.87 v1(3765,4735) ; R30.1 3800,4888.07 v1(3821.54,4866.54)
  Bottom Layer w10: v1(3765,4735) 3746.91,4716.91 3736.91,4716.91 3729.84,4723.98 3729.84,4733.98 3754.86,4759 3816.63,4759 3833.07,4775.44 3833.07,4855 v1(3821.54,4866.54)
$1N27720: R29.1 U11.54 | length 366.6
  Top Layer w10: v1(3725,4660) 3740,4675 3740,4699.63 U11.54 ; R29.1 3865,4877.96 v1(3865,4860)
  Bottom Layer w10: v1(3725,4660) 3735,4660 3742.01,4667.01 3742.01,4669.52 3755.48,4682.99 3757.99,4682.99 3818,4743 3833.25,4743 3859.07,4768.82 3859.07,4854.07 v1(3865,4860)
$1N48925: R31.1 R32.2 U48.5 | length 137.9
  Top Layer w10: U48.5 3465,4174.66 R31.1 3470.34,4190.68 R32.2
$1N49024: C33.1 U48.6 | length 161.4
  Top Layer w10: C33.1 3400,4008.54 3400,4097.64 U48.6
$1N49028: C33.2 L2.2 U48.2 | length 112
  Top Layer w10: U48.2 3465,3986.46 C33.2 3466.46,3946.11 L2.2
$1N49243: C36.2 R33.2 R34.1 | length 487.6
  Top Layer w6: R33.2 3525.34,4060.34 3578.54,4113.54 C36.2 3599.53,4239.01 3704.94,4239.01 3730.93,4265 R34.1
$1N49255: C36.1 R34.2 R35.1 U48.4 | length 533.7
  Top Layer w6: U48.4 3502.4,4198.33 3510.06,4205.99 3535.99,4205.99 3555,4225 3555,4244.65 3554,4245.65 3554,4274.35 3559.27,4279.61 3597.81,4279.61 3617.43,4260 C36.1 3626.46,4265 R34.2 3720.34,4300 3765,4300 3775,4290 3775,4229.66 R35.1
+3.3V: C4.2 C8.1 C18.1 C26.2 C27.2 C28.2 C29.2 C30.2 L1.2 R12.1 R13.1 R14.1 R16.2 R17.2 R25.1 R31.2 U1.3 U1.4 U2.8 U3.1 U3.10 U3.22 U3.33 U3.42 U3.43 U3.44 U3.48 U3.49 U6.4 U11.16 U11.34 U11.52 U11.63 U44.8 U48.3 | length 2677.7
  Top Layer w6: C27.2 3485,4248.54 3485,4310 3473.54,4321.46 C28.2 C29.2 C30.2
  Top Layer w8: v1(4075,4436.68) 4104.46,4466.14 U44.8
  Top Layer w10: C30.2 C26.2 3469.34,4375.01 U11.16 3540.01,4375.01 v1(3550,4385) ; v1(3452.96,4080.99) 3467.1,4066.85 3480.02,4066.85 U48.3@3502.4,4044.47 ; U48.3 U48.3@3502.4,4044.47 ; R31.2 3529.66,4102.02 3502.4,4074.76 U48.3@3502.4,4044.47 ; v1(3550,4660) 3563.02,4673.02 U11.63 ; v1(3765,4660) 3775,4660 3779.55,4664.55 U11.52 ; U11.34 3885.96,4394.7 3902.28,4378.39 3938.39,4378.39 3952.04,4392.04 R17.2 3966.66,4400 U6.4 v1(4075,4436.68) ; R16.2 v1(3980,4530) ; C8.1 4098.9,4331.46 4100,4330.36 ; R25.1 4094.92,4206.96 4094.92,4210.18 4100,4215.26 4100,4330.36 ; U44.8 4100,4442.5 4100,4330.36 ; U1.3 4259.53,4588.64 ; U1.4 4259.53,4588.64 ; v1(4280,4580) 4271.36,4588.64 4259.53,4588.64
  Bottom Layer w6: U3.22 3836.21,4261.25 3844.3,4253.16 3844.3,4150 3848.55,4145.76 3908.28,4145.76 v1(3914.06,4151.53) ; U3.33 3914.06,4464.06 v1(3980,4530)
  Bottom Layer w8: v1(4035,4205) 4035,4240 4056.25,4261.25 U3.49
  Bottom Layer w10: R14.1 3602.04,4855 R13.1 ; R13.1@3607.4,4880.43 3660,4933.03 v1(3660,4940) 3645,4925 R12.1 ; L1.2 3905.58,5015.58 3994.61,5104.61 U2.8 4070.39,5104.61 4083.02,5091.98 C4.2 4101.56,5096.98 v1(4113.02,5096.98) ; U3.10 v1(3914.06,4151.53) ; v1(4053.47,4151.53) 4055.79,4149.21 U3.1 ; U3.42@4055.79,4392.44 4076.21,4392.44 ; v1(4075,4436.68) 4075,4393.65 4076.21,4392.44 ; U3.49 U3.48 ; U3.44 U3.43 4093.19,4375.47 4076.21,4392.44
+5V: C35.2 D30.2 L2.1 R26.2 R33.1 TRACKPAD.8 | length 2777.8
  Top Layer w6: R33.1 3590,3980 v1(3637.5,3932.5)
  Top Layer w10: L2.1 3457.45,3900 3544.83,3900 ; C35.2 3544.83,3928.71 3544.83,3900 ; R26.2 3667.04,3962.04 v1(3637.5,3932.5) 3605,3900 3544.83,3900
  Top Layer w15: D30.2 4495,4443.37 v1(4495,4395)
  3.3V w15: v1(3637.5,3932.5) 3719.51,4014.51 3720.56,4014.51 3735.49,4029.44 3735.49,4030.49 3772.52,4067.52 3772.52,4080.23 3787.46,4095.16 3829.56,4095.16 3849.06,4114.67 3849.06,4134.08 3942.87,4227.89 3963.99,4227.89 3978.92,4242.82 3978.92,4273.92 4000,4295 4045,4295 4145,4395 v1(4495,4395)
  Bottom Layer w15: TRACKPAD.8@3490.42,4993.98 3453.98,4993.98 3415,4955 3415,4946.05 3414.51,4945.56 3414.51,4924.44 3415,4923.95 3415,4555 3475,4495 3475,4095 3531.52,4038.48 3531.52,4019.41 3546.46,4004.48 3565.52,4004.48 v1(3637.5,3932.5)
BACKLIGHT+: BACKLIGHT.3 BACKLIGHT.4 Q1.3 | length 775.8
  Top Layer w10: BACKLIGHT.4 BACKLIGHT.3
  Top Layer w15: Q1.3 4435,4555 4465,4525 4465,4510 4440,4485 4440,4438.45 4442.89,4435.56 4442.89,4435.07 4465.61,4412.35 4465.61,4345.61 4455,4335 4425.38,4335 4400,4309.62 4400,4225 4450,4175 4450,4095 4435.32,4080.32 BACKLIGHT.3
CAPS-: KEYBOARD.26 Q14.3 | length 86
  Bottom Layer w6: Q14.3 3761.54,4055.43 KEYBOARD.26
CC1: C1.2 R18.2 U1.10 U1.11 U47.A5 | length 570.2
  Top Layer w10: v1(4050,4760) 4070,4760 4097.07,4787.07 4137.93,4787.07 4145,4780 4145,4757.04 R18.2 4153.96,4748.08 C1.2 4183.64,4677.82 U1.11 4200.47,4681.36 U1.10 ; v1(4180,4894.09) 4209.97,4894.09 4210.51,4894.63 4241.79,4894.63 U47.A5
  Bottom Layer w10: v1(4050,4760) 4050,4835.8 4105,4890.8 4176.7,4890.8 v1(4180,4894.09)
CC2: C2.1 R19.2 U1.1 U1.14 U47.B5 | length 433.7
  Top Layer w10: v1(4150,4605.47) 4189.86,4605.47 4198.38,4596.95 4202.01,4596.95 U1.1
  Bottom Layer w10: v1(4150,4605.47) 4150,4716.46 C2.1 4128.96,4773.08 R19.2 4119.54,4816.19 4121.04,4817.69 4121.04,4828.18 4134.51,4841.65 4153.56,4841.65 4156.83,4838.38 U47.B5
EINK_OLED_USB_M: GLYPH.15 R23.1 | length 906.2
  Top Layer w6: R23.1 3405,4502.96 3405,4900 v1(3440,4935) ; v1(3450,4805) 3450,4890 3470.99,4910.99 3528.7,4910.99 3529.69,4910 3530,4910 3566.42,4946.42 GLYPH.15
  Bottom Layer w6: v1(3440,4935) 3440,4815 v1(3450,4805)
EINK_OLED_USB_P: GLYPH.16 R22.1 | length 577.5
  Top Layer w6: R22.1 3425,4527.96 3425,4881.97 3466.02,4922.99 3526.02,4922.99 3549.01,4945.99 3549.01,5011.55 GLYPH.16
GND: B1.1 B2.2 BACKLIGHT.1 BACKLIGHT.2 C1.1 C2.2 C3.2 C4.1 C5.2 C6.2 C7.2 C8.2 C14.1 C15.1 C18.2 C20.1 C21.1 C22.1 C23.1 C24.1 C25.2 C26.1 C27.1 C28.1 C29.1 C30.1 C35.1 GLYPH.8 GLYPH.9 GLYPH.10 GLYPH.11 GLYPH.12 Q2.2 Q14.2 R4.1 R6.2 R7.1 R8.1 R9.2 R10.1 R18.1 R19.1 R32.1 R35.2 TRACKPAD.1 U1.8 U1.9 U2.5 U2.10 U3.19 U3.57 U5.2 U5.4 U6.2 U6.5 U31.2 U31.4 U44.4 U47.25 U47.26 U47.A1 U47.A12 U47.B1 U47.B12 U48.1 | length 4410.7
  Top Layer w6: C27.1 C29.1 ; v1(3445,4245) 3445,4248.54 C29.1 ; C28.1 C29.1 ; C35.1 v1(3586.46,3945) ; v1(3618.1,4298.33) 3704.5,4298.33 3716.19,4310.02 3769.15,4310.02 3785.02,4294.15 3785.02,4229.64 R35.2 ; B2.2@3661.48,4210.3 3660,4208.82 3660,4087.6 v1(3662.6,4085)
  Top Layer w8: v1(4080,4665) 4080,4676.46 C1.1 ; U47.A12 4270.11,4734.11 4270.11,4704.52 ccw(c4285.92,4704.52) 4275,4693.08 v1(4275,4690)
  Top Layer w10: C30.1 v1(3440.48,4422.27) C26.1 ; v1(3422.99,4080) 3422.99,4039.37 U48.1 ; R4.1 3520,4819.66 v1(3520,4840) ; R32.1 3524.66,4299.66 3540,4315 3601.42,4315 v1(3618.1,4298.33) ; U5.4 3571.27,4817.3 3618.51,4864.54 U5.2 v1(3656.47,4846.47) ; C24.1 C20.1 C21.1 C22.1 C23.1 4006.61,4789.85 4006.61,4748.44 4000,4741.82 v1(4000,4720) 3974.66,4720 R7.1 ; U6.2 3977.75,4462.27 U6.5 4021.28,4487.86 ; R6.2 3960.34,4590.34 v1(3970,4600) 4005,4565 4005,4504.15 4021.28,4487.86 ; v1(3953.43,4253.38) 4029.84,4253.38 C8.2 ; C18.2 4043.6,4487.86 4021.28,4487.86 ; R9.2 4115.46,4647.5 R18.1 ; U1.9 U1.8 4266.36,4681.36 v1(4275,4690) ; U47.A1@4244.55,4976.14 4244.55,5007.64 U47.25 4245,5012.02 v1(4245,5040) ; v1(4265,4170) 4275,4160 4291.61,4160 ; U44.4 4291.61,4227.69 4291.61,4160 ; B1.1 4291.61,4160 ; R10.1 4417.4,4370.36 Q2.2 v1(4417.4,4425) ; BACKLIGHT.2 v1(4382.68,4138.21) BACKLIGHT.1
  Top Layer w15: GLYPH.12@3626.16,5013.82 GLYPH.11 GLYPH.10 GLYPH.9 ; v1(3690,4905) 3685.49,4909.51 3685.49,4950.56 3684.53,4951.52 GLYPH.9 ; GLYPH.8@3703.53,5013.82 GLYPH.9
  3.3V w15: v1(3656.47,4846.47) 3690,4880 v1(3690,4905)
  Bottom Layer w6: TRACKPAD.1 3628.9,5088.9 v1(3635,5095) ; C14.1 3720.09,4170.07 3758.3,4208.28 3785.39,4208.28 3788.29,4211.18 3810.84,4211.18 U3.19
  Bottom Layer w10: C15.1 3591.77,4236.77 U31.2 3603.58,4283.81 v1(3618.1,4298.33) 3666.57,4346.8 U31.4 3709.57,4377.99 C25.2 ; v1(3662.6,4085) 3658.23,4089.37 Q14.2 3597.6,4117.4 3580,4135 3580,4155 3595.07,4170.07 C14.1 ; R8.1 U2.5 3848.84,5144.41 v1(3969.58,5144.41) ; v1(3988.02,5065.23) U2.10 4053.31,5065.23 C4.1 4121.49,5073.99 4122.55,5073.99 4136.46,5087.9 C3.2 ; C2.2 4086.04,4781.92 R19.1 4095,4792.04 v1(4095,4825) ; C7.2 C6.2 C5.2 4194.93,4476.53 v1(4194.93,4516.53) ; U47.B1 4244.55,4728.11 4242.58,4726.14 4270.16,4698.56 ccw(c4285.89,4704.49) 4275,4691.68 v1(4275,4690) ; U47.B12@4244.55,4976.14 4244.55,5006.49 4244.55,5039.55 v1(4245,5040)
  Bottom Layer w15: v1(3970,4600) 3970,4690 v1(4000,4720)
INT_USBC_CTRL: U1.5
KBRD0: KEYBOARD.1 U3.15 | length 937.3
  Top Layer w6: v1(3823.57,4125.22) 3823.57,4091.96 3830.02,4085.51 3830.02,4050.85 3814.15,4034.98 3785,4035 3770,4020 3770,3935 3775,3930 4091.69,3930.02 4112.69,3951.02 4203.98,3951.02 v1(4250,3905)
  Bottom Layer w6: U3.15 3813.88,4150.81 3813.88,4134.91 v1(3823.57,4125.22) ; v1(4250,3905) 4265,3905 4285.03,3925.03 4285.03,3925.26 4290.3,3930.52 4290.52,3930.52 4295,3935 4295,3995 4285.79,4004.21 KEYBOARD.1
KBRD1: KEYBOARD.2 U3.29 | length 942.9
  Top Layer w6: v1(3862.12,4332.1) 3845,4314.99 3845,4250 3850,4245 3850,4120 3840,4110 3840,3975 3865,3950 4040,3950 4070.99,3980.99 4088.7,3980.99 4108.65,3961.04 4238.96,3961.04 v1(4250,3950)
  Bottom Layer w6: U3.29 3851.06,4343.16 v1(3862.12,4332.1) ; KEYBOARD.2 4235,4003.19 4235,3965 v1(4250,3950)
KBRD2: KEYBOARD.3 U3.16 | length 902.8
  Top Layer w6: v1(3792.89,4129.01) 3797.89,4124.01 3797.89,4108.47 3813.55,4092.81 3813.55,4087.81 3820,4081.37 3820,4061.97 3804.84,4046.81 3782.64,4046.81 3759.98,4024.15 3759.98,3930.85 3770.85,3919.98 4095.82,3919.98 4116.84,3941.01 4183.68,3941.01 4200.99,3923.7 4200.99,3919.01 4208.26,3911.74 4213.26,3911.74 v1(4215,3910)
  Bottom Layer w6: v1(3792.89,4129.01) 3790.42,4126.54 3788.46,4126.54 3781.49,4133.51 3781.49,4160.76 3787.49,4166.76 U3.16 ; KEYBOARD.3 4215,4003.5 v1(4215,3910)
KBRD3: KEYBOARD.4 U3.35 | length 1215.3
  Bottom Layer w6: U3.35 3948.37,4395.98 3948.37,4468.37 4000.99,4520.99 4000.99,4566.99 4032.49,4598.49 4032.49,4635 4036.73,4639.24 4080.76,4639.24 4091.98,4628.02 4091.98,4578.4 4123.4,4546.98 4166.6,4546.98 4194.62,4575 4250,4575 4305,4520 4305,4145 4194.61,4034.61 KEYBOARD.4
KBRD4: KEYBOARD.5 U3.17 | length 873.8
  Top Layer w6: v1(3798.01,4069.67) 3793.34,4065 3784.86,4065 3749.38,4029.52 3749.38,3925.62 3764.98,3910.02 4100.02,3910.02 4120.99,3930.99 4154.01,3930.99 v1(4175,3910)
  Bottom Layer w6: v1(3798.01,4069.67) 3798.01,4095 3785,4108.02 3784.19,4108.02 3770,4122.21 3770,4169.43 3783.08,4182.51 U3.17 ; KEYBOARD.5 4174.92,3910.08 v1(4175,3910)
KBRD5: KEYBOARD.6 U3.30 | length 831
  Top Layer w6: v1(3886.63,4350.01) 3889.46,4347.19 3889.46,4259.46 3865,4235 3865,3985 3890,3960 4035,3960 4066.01,3991.01 4092.84,3991.01 4111.93,3971.93 4117.93,3971.93 4155,4009 v1(4155,4040)
  Bottom Layer w6: U3.30 3866.81,4370.61 3886.63,4350.78 v1(3886.63,4350.01) ; v1(4155,4040) 4155.24,4039.76 KEYBOARD.6
KBRD6: KEYBOARD.7 U3.18 | length 841.2
  Top Layer w6: v1(3739.37,4131.77) 3739.37,3920.63 3760,3900 4125,3900 v1(4135,3910)
  Bottom Layer w6: v1(3739.37,4131.77) 3750,4142.41 3750,4185.82 3762.44,4198.26 U3.18 ; v1(4135,3910) 4135,4003.66 KEYBOARD.7
KBRD7: KEYBOARD.8 U3.34 | length 628.7
  Top Layer w6: v1(3955,4350) 3915,4310 3915,4250 3890,4225 3890,4088.45 3908.45,4070 4045,4070 4050,4065 v1(4075,4065)
  Bottom Layer w6: U3.34 3929.8,4369.89 3940.99,4358.7 3940.99,4354.41 3945.4,4350 v1(3955,4350) ; v1(4075,4065) 4075,4045.08 4091.14,4028.94 4105.81,4028.94 4111.07,4023.68 4111.07,4009.01 KEYBOARD.8
KBRD8: KEYBOARD.9 U3.27 | length 1319.4
  Top Layer w6: v1(3795,3951.01) 3806.01,3940 4060,3940 v1(4080,3960)
  Bottom Layer w6: v1(3795,3951.01) 3693.99,3951.01 3527.01,4117.99 3527.01,4394.52 3541.09,4408.6 3771.4,4408.6 3778.47,4401.53 3778.47,4339.99 U3.27 ; v1(4080,3960) 4096.18,3976.18 KEYBOARD.9
KBRD9: KEYBOARD.10 U3.31 | length 1420.2
  Bottom Layer w6: U3.31 3882.56,4415.7 3869.62,4428.64 3532.79,4428.64 3506.98,4402.82 3506.98,4109.69 3686.67,3930 3701.2,3930 3701.72,3930.52 3724.91,3930.52 3730.17,3925.26 3730.17,3925 3760.17,3895 3981.96,3895 4076.5,3989.54 KEYBOARD.10
KBRD10: KEYBOARD.11 U3.28 | length 1322.6
  Bottom Layer w6: U3.28 3788.67,4355.74 3788.48,4355.93 3788.48,4405.68 3775.54,4418.62 3536.94,4418.62 3516.99,4398.67 3516.99,4113.84 3690.27,3940.56 3729.03,3940.56 3740.19,3929.41 3740.19,3929.15 3762.17,3907.17 3979.97,3907.17 4056.81,3984.02 KEYBOARD.11
KBRD11: KEYBOARD.12 U3.32 | length 711.4
  Top Layer w6: v1(3920,4350) 3920,4344.53 3900.47,4325 3900.47,4254.46 3876.02,4230 3876.02,3990.29 3895.29,3971.02 4025,3971.02 4040,3986.02 v1(4040,4045)
  Bottom Layer w6: U3.32 3900.67,4390.79 3900.67,4365.67 3916.33,4350 v1(3920,4350) ; KEYBOARD.12 4040,4007.11 v1(4040,4045)
KBRD12: KEYBOARD.13 U3.2 | length 118.8
  Bottom Layer w6: KEYBOARD.13 4017.44,4067.44 4040.04,4090.04 U3.2
KBRD13: KEYBOARD.14 U3.3 | length 120.4
  Bottom Layer w6: KEYBOARD.14 3997.76,4062.76 4024.29,4089.29 U3.3
KBRD14: KEYBOARD.15 U3.4 | length 122
  Bottom Layer w6: KEYBOARD.15 3980,4006.15 3980,4060 4008.54,4088.54 U3.4
KBRD15: KEYBOARD.16 U3.5 | length 123.6
  Bottom Layer w6: KEYBOARD.16 3958.39,4053.39 3992.8,4087.8 U3.5
KBRD16: KEYBOARD.17 U3.6 | length 125.3
  Bottom Layer w6: KEYBOARD.17 3938.7,4052.72 3977.05,4091.07 U3.6
KBRD17: KEYBOARD.20 U3.9 | length 130.2
  Bottom Layer w6: KEYBOARD.20 3879.65,4040.91 3929.8,4091.06 U3.9
KBRD18: KEYBOARD.19 U3.8 | length 128.5
  Bottom Layer w6: KEYBOARD.19 3900.28,4005.17 3900.28,4045.8 3945.55,4091.07 U3.8
KBRD19: B2.1 KEYBOARD.18 U3.7 | length 500.9
  Top Layer w6: B2.1 3703.39,4033.39 v1(3710,4040)
  Bottom Layer w6: v1(3710,4040) 3710,4020 3755,3975 3889.8,3975 3894.29,3979.49 3908.96,3979.49 3914.22,3984.75 3914.22,3999.42 KEYBOARD.18 3919.02,4048.79 3961.3,4091.07 U3.7
  Bottom Layer w10: U3.7 v1(3961.3,4151.53)
KBRD20: KEYBOARD.21 U3.11 | length 125.3
  Bottom Layer w6: KEYBOARD.21 3859.96,4052.72 3898.31,4091.07 U3.11
KBRD21: KEYBOARD.22 U3.12 | length 126.9
  Bottom Layer w6: KEYBOARD.22 3840.28,4048.79 3882.56,4091.07 U3.12
KBRD22: KEYBOARD.23 U3.13 | length 128.5
  Bottom Layer w6: KEYBOARD.23 3820.59,4044.85 3863.98,4088.24 3863.98,4108.98 3866.81,4111.81 U3.13
KBRD23: KEYBOARD.24 U3.14 | length 130.2
  Bottom Layer w6: KEYBOARD.24 3800.91,4040.91 3851.06,4091.06 U3.14
KBRD_CTRL: R11.1 U3.41 | length 584.8
  Top Layer w15: v1(4355,4230) 4367.04,4242.04 R11.1
  GND w15: v1(4120,4510) 4355,4275 v1(4355,4230)
  Bottom Layer w10: U3.41 4040.04,4430.04 4052.01,4442.01 4052.01,4446.21 4065.48,4459.68 4069.68,4459.68 v1(4120,4510)
KBRDUSB_M: R21.1 U3.46 | length 964.6
  Top Layer w6: v1(3465,4565) R21.1
  GND w6: v1(3465,4565) 3465,4652.26 3469.24,4656.5 3496.53,4656.5 3530.03,4623 3585.03,4623 3841.12,4366.91 3841.12,4323.41 3853.42,4311.11 3870.81,4311.11 3878.5,4318.8 3998.49,4318.8 4021.72,4342.03 v1(4021.72,4348.51)
  Bottom Layer w6: v1(4021.72,4348.51) 4033.74,4336.48 4033.74,4330.54 4057.66,4306.63 4063.66,4306.63 4065.53,4308.5 U3.46
KBRDUSB_P: R20.1 U3.47 | length 967.6
  Top Layer w6: v1(3460,4760) 3460,4727.04 R20.1@3465,4722.04
  GND w6: v1(3460,4760) 3460,4677.74 3469.24,4668.5 3501.5,4668.5 3535,4635 3590,4635 3680.56,4544.44 ccw(c3687.63,4551.51) 3694.71,4544.44 3704.2,4553.93 cw(c3711.27,4546.86) 3718.34,4539.79 3708.85,4530.29 ccw(c3715.92,4523.22) 3708.85,4516.15 3853.99,4371.01 3963.68,4371.01 3989.79,4344.89 v1(3989.79,4339.79)
  Bottom Layer w6: v1(3989.79,4339.79) 4006.2,4323.39 4023.92,4323.39 4052.69,4294.63 4063.66,4294.63 4065.53,4292.75 U3.47
QSPI_SCLK: U3.52 U44.6 | length 592.3
  Top Layer w6: U44.6 4240,4482.5 v1(4240,4545)
  Bottom Layer w6: U3.52 4254.01,4214.01 4265,4225 4264.98,4500.33 4254.01,4511.3 4254.01,4530.99 v1(4240,4545)
QSPI_SD0: U3.53 U44.5 | length 548.2
  Top Layer w6: U44.5 4275,4467.5 v1(4275,4520)
  Bottom Layer w6: U3.53 4258.26,4198.26 4275,4215 v1(4275,4520)
QSPI_SD1: U3.55 U44.2 | length 213.3
  Top Layer w6: U44.2 4175,4244.3 4175,4170 v1(4195,4150)
  Bottom Layer w6: U3.55 4178.24,4166.76 v1(4195,4150)
QSPI_SD2: U3.54 U44.3 | length 234.4
  Top Layer w6: U44.3 4230,4239.3 v1(4230,4160)
  Bottom Layer w6: U3.54 4207.49,4182.51 v1(4230,4160)
QSPI_SD3: U3.51 U44.7 | length 590.6
  Top Layer w6: v1(4160,4525) 4160,4479.79 U44.7
  Bottom Layer w6: U3.51 4229.76,4229.76 4245,4245 4245,4475 4220,4500 4220,4535 4215.76,4539.24 4174.24,4539.24 v1(4160,4525)
QSPI_SS: B1.2 R25.2 U3.56 U44.1 | length 357.3
  Top Layer w6: U44.1 4140,4229.3 4140,4155 v1(4165,4130)
  Top Layer w10: B1.2 4118.39,4193.65 R25.2 4123.65,4201.61 U44.1
  Bottom Layer w6: U3.56 4143.98,4151.02 v1(4165,4130)
SCL_USBC_CTRL: U1.6
SDA_USBC_CTRL: U1.7
SSRXN1: U11.59 U47.A3 U47.B3 | length 1871.7
  Top Layer w10: v1(3610,4660) 3621.76,4660 3641.76,4680 U11.59 ; v1(4055,4915) 4090,4950 4130,4950 ; v1(4145,5024.95) 4124.95,5024.95 4110,5010 4110,4970 4130,4950 ; U47.A3 4176.71,4936.8 4163.5,4950 4130,4950
  Bottom Layer w10: v1(3610,4660) 3610,4682.01 3624.5,4696.51 3624.5,4781.98 3818.52,4976 4089.43,4976 4138.37,5024.95 v1(4145,5024.95) ; v1(4055,4915) 3985,4845 3985,4780 4077.01,4687.99 4089.52,4687.99 4127.01,4650.51 4127.01,4595.95 4140.48,4582.48 4159.52,4582.48 4162.05,4585 4165,4585 4175,4595 4175,4620 4165,4630 4165,4770 4194.01,4799.01 U47.B3
SSRXP1: U11.58 U47.A2 U47.B2 | length 1318.9
  Top Layer w10: v1(3655,4660) 3661.44,4666.44 U11.58 ; v1(4145,4994.95) 4183.46,4956.48 U47.A2
  3.3V w10: v1(4145,4994.95) 4156.96,4994.95 4172.01,5010 4172.01,5027.01 4190,5045 4205,5045 4220,5030 4220,4975 4255,4940 4255,4819.31 v1(4295,4779.31)
  Bottom Layer w10: v1(3655,4660) 3655,4682.01 3640.5,4696.51 3640.5,4775.36 3825.14,4960 4110.05,4960 v1(4145,4994.95) ; U47.B2 v1(4295,4779.31)
SSTXN1: C9.1 U47.A10 U47.B10 | length 1059
  Top Layer w10: C9.1 3685,4860 3765,4940 v1(3765,4960) ; U47.A10 4247.38,4801.8 4278.66,4801.8 4292.29,4815.42 v1(4296.37,4815.42) 4304.54,4823.59 4304.54,4925.46 v1(4295,4935)
  GND w10: v1(3765,4960) 3765,4930.07 3777.07,4918 3863.64,4918 3990.64,4791 4025.86,4791 4033.85,4798.99 4066.15,4798.99 4074.14,4791 4271.96,4791 v1(4296.37,4815.42)
  Bottom Layer w10: U47.B10 4246.38,4935 v1(4295,4935)
SSTXP1: C10.1 U47.A11 U47.B11 | length 1111.5
  Top Layer w10: C10.1 3735,4825 v1(3770,4860) ; v1(4190,4740) 4204.07,4754.07 4204.07,4770.09 4210.51,4776.52 4226.52,4776.52 4229.31,4779.31 U47.A11
  3.3V w10: v1(4190,4740) 4190,4755 4230,4795 4230,4915 4195,4950 v1(4195,5010)
  GND w10: v1(3770,4860) 3770,4894.93 3777.07,4902 3857.02,4902 3984.02,4775 4032.48,4775 4040.48,4782.99 4059.52,4782.99 4067.52,4775 4185,4775 4190.86,4769.14 4190.86,4740.86 v1(4190,4740)
  Bottom Layer w10: v1(4195,5010) 4185,5000 4185,4965 4193.52,4956.48 U47.B11
TOUCHPAD_ID: TRACKPAD.6 U3.37 | length 1139.5
  GND w6: v1(3475,4885) 3475,4895 3495,4915 3545,4915 3685,4775 3775,4775 3840,4710 3885,4710 3945.76,4649.24 3945.76,4594.24 3950,4590 3950.31,4590 3961.3,4579.01 3975.99,4579.01 4015,4540 4045.31,4540 v1(4063.56,4558.24)
  Bottom Layer w6: v1(3475,4885) 3487.94,4897.94 3487.94,4902.11 3530.47,4944.63 TRACKPAD.6 ; U3.37 3979.87,4395.98 3979.87,4433.56 4035,4488.68 4035,4529.69 v1(4063.56,4558.24) 4062.5,4559.3 v1@4062.5,4562.5
TOUCHPAD_INT: R12.2 TRACKPAD.2 U3.40 | length 1028.6
  GND w6: v1(3715.02,4966.3) 3715.02,4865.02 3850,4730.03 3893.3,4730.03 3933.31,4690.02 4009.67,4690.02 4080.99,4618.7 4080.99,4604.01 4092.5,4592.5 4092.5,4545 v1(4102.5,4535)
  Bottom Layer w6: R12.2 3606.92,4938.96 3606.92,4939.35 3612.18,4944.61 3629.3,4944.61 3634.69,4950 3635,4950 3651.3,4966.3 v1(3715.02,4966.3) ; 3609.21,4941.64 TRACKPAD.2 ; U3.40 4024.29,4435.48 4060.5,4471.69 4061.69,4471.69 4099.01,4509.01 4099.01,4518.7 4102.5,4522.19 v1(4102.5,4535)
TOUCHPAD_SCL: R13.2 TRACKPAD.3 U3.39 | length 1121.3
  GND w6: v1(3520,4890) 3555,4890 3745,4700 3875,4700 3935,4640 3935,4530 3965,4500 4005,4500 4020,4515 v1(4075,4515)
  Bottom Layer w6: v1(3520,4890) 3563.74,4890 3565.63,4888.11 ; R13.2 3572.84,4879.88 3572.84,4880.9 3572.84,4939.35 3589.53,4956.04 TRACKPAD.3 ; U3.39 4008.54,4433.89 4056.35,4481.71 4056.71,4481.71 4075,4500 v1(4075,4515)
  Bottom Layer w10: 3565.63,4888.11 R13.2@3572.84,4880.9
TOUCHPAD_SDA: R14.2 TRACKPAD.4 U3.38 | length 1360.9
  GND w6: v1(3475,4845) 3445,4875 3445,4884.69 3466.3,4905.99 3471.83,4905.99 3490.85,4925.02 3607.63,4925 3747.62,4785.02 3779.15,4785.02 3844.15,4720.02 3889.15,4720.02 3929.16,4680 3980,4680 v1(4060,4600)
  Bottom Layer w6: v1(3475,4845) 3499.01,4869.01 3499.01,4898.7 3555.15,4954.84 3569.84,4954.84 TRACKPAD.4 ; U3.38 3995.61,4395.97 3995.61,4418.53 3998.52,4421.43 3998.52,4438.04 4055,4494.52 4055,4505.31 4054.01,4506.3 4054.01,4523.7 4066.3,4535.99 4070.99,4535.99 4085,4550 4085,4571.22 4081.97,4574.25 4081.97,4603.03 4078.94,4600 v1(4060,4600)
  Bottom Layer w10: v1(3475,4845) 3497.96,4822.04 R14.2
USB_UP+: R30.2 U47.A6 U47.B6 | length 435
  Top Layer w10: 3845,4932.04 3855,4932.04 3931.94,4855.1 4201.15,4855.1 4206.88,4860.83 4241.75,4860.83 4244.55,4858.03
USB_UP-: R29.2 U47.A7 U47.B7 | length 508.6
  Top Layer w10: 3800,4932.04 3800,4954 3806,4960 3854.34,4960 3943.24,4871.1 4194.52,4871.1 4201.14,4877.72 4244.55,4877.72
VBUS: C3.1 D1.1 D2.1 GLYPH.1 GLYPH.2 GLYPH.3 GLYPH.4 GLYPH.17 GLYPH.18 GLYPH.19 GLYPH.20 R5.1 U1.2 U2.2 U2.7 | length 2176.1
  Top Layer w10: R5.1 4042.52,4650 4127.52,4565 4225,4565 4230,4570 U1.2
  Top Layer w15: GLYPH.20 GLYPH.19 GLYPH.18 ; GLYPH.17@3526.37,5013.82 GLYPH.18 ; v1(3755,5084.92) 3755,5057.83 3756,5056.83 ; GLYPH.1 GLYPH.2 GLYPH.3 3783.64,5032.82 3783.64,5048.93 3775.75,5056.83 3756,5056.83 ; v1(3965,4905) 3998.37,4905 D2.1 ; R5.1 4040,4650.34 4040,4720 4023.13,4736.87 4023.13,4806.87 v1(4015,4815) 4048.62,4815 D1.1 ; GLYPH.18 3507.37,5029.94 3534.26,5056.83 3756,5056.83
  GND w15: v1(3965,4905) 4015,4855 ; v1(4015,4815) 4015,4855 ; v1(4190,5110) 4175,5110 4085,5020 4005,5020 3989.39,5035.61 3925.61,5035.61 3915,5025 3915,4890 3950,4855 4015,4855
  Bottom Layer w15: v1(3755,5084.92) U2.2 3946.15,5084.92 3985.53,5124.3 U2.7 4082.84,5124.3 C3.1 4107.42,5148.88 4107.42,5151.22 4115.32,5159.11 4175.89,5159.11 4190.61,5144.39 4190.61,5110.61 v1(4190,5110)
pads on no net: BACKLIGHT.5 BACKLIGHT.6 GLYPH.5 GLYPH.6 GLYPH.7 GLYPH.13 GLYPH.14 GLYPH.21 GLYPH.22 KEYBOARD.27 KEYBOARD.28 TRACKPAD.5 TRACKPAD.7 TRACKPAD.9 TRACKPAD.10 U1.15 U2.4 U2.6 U2.9 U3.24 U3.25 U11.3 U11.4 U11.6 U11.7 U11.11 U11.12 U11.14 U11.15 U11.17 U11.18 U11.19 U11.20 U11.22 U11.23 U11.24 U11.25 U11.26 U11.27 U11.29 U11.30 U11.32 U11.33 U11.35 U11.36 U11.39 U11.40 U11.41 U11.42 U11.43 U11.44 U11.45 U11.46 U11.47 U11.50 U11.60 U11.65 U44.9 U47.A8
copper on no net: | length 1080.8
  3.3V w6: 3508.81,4386.79 3555.12,4340.48 3795,4580.36 3795,4665.74 3773.8,4686.93 3516.43,4686.93 3508.81,4679.32 3508.81,4386.79

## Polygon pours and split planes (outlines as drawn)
+3.3V on 3.3V (solid, remove dead copper): 3380,5180 4530,5180 4530,3880 3380,3880
GND on GND (solid, remove dead copper): 3380,5180 4530,5180 4530,3880 3380,3880

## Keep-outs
Board Outline Layer:
  lines w5.98: 4323.36,3880 4530,3880 4530,4636.94 4326,4636.94
  lines w6: 4321.36,4704.52 4326,4704.52 4326,4636.94 ; 4321.36,5031.29 4321.36,5180 3380,5180 3380,3880 4323.36,3880

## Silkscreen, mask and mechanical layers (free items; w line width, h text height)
Top Silkscreen Layer:
  text "Thanks Arya!" at 3975,5105 h60
  text "Built and designed" at 3720,3935 h60
  text "with ♡ by JJ Shapiro" at 3725,3885 h60
Bottom Silkscreen Layer:
  text "And the universe said I love you... /  Because you are love." at 3350,4995 h70 r90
